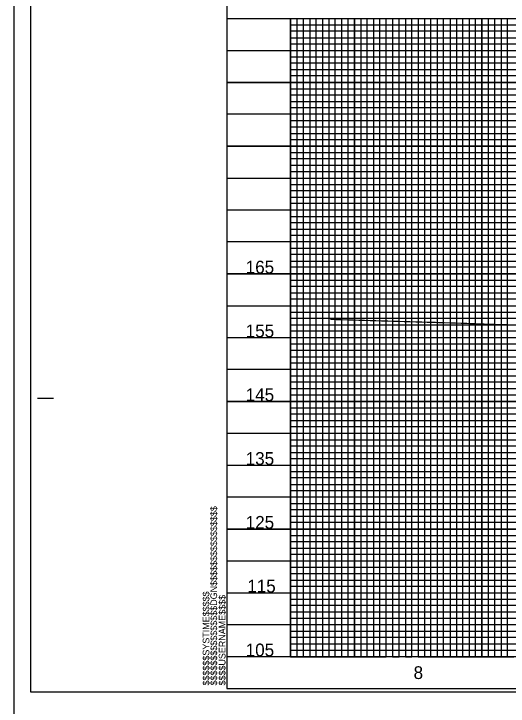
# Model space of a CAD drawing. Extents: x 573468 to 580768, y -57414 to -51768.
# Drawn here: x 578678 to 579066, y -56302 to -55760 of the extents above; entities that cross this region are included whole.
import ezdxf

# ---------------------------------------------------------------- set-up
doc = ezdxf.new("R2010")
doc.units = 0
for name, color, linetype in [('Exist Vertical Profile Ground Line', 7, 'Continuous'), ('Exist Vertical Profile Horizontal Axis Label Major', 7, 'Continuous'), ('Exist Vertical Profile Vertical Axis Label', 7, 'Continuous'), ('Sheet Cutting Line CELL', 7, 'Continuous'), ('Sheet DOT Grid CELL', 7, 'Continuous'), ('Sheet Layout Profile Border Port 2', 7, 'Continuous'), ('Sheet Plot Border Inside CELL', 7, 'Continuous'), ('Sheet Plot Border Outside CELL', 7, 'Continuous'), ('Sheet Profile CELL', 7, 'Continuous'), ('Sheet Profile Grid Major CELL', 7, 'Continuous'), ('Sheet Profile Grid Middle CELL', 7, 'Continuous'), ('Sheet Profile Grid Minor CELL', 7, 'Continuous')]:
    doc.layers.add(name, color=color, linetype=linetype)

msp = doc.modelspace()

# ---------------------------------------------------------------- linework, layer by layer
at = {"layer": 'Exist Vertical Profile Ground Line'}
msp.add_lwpolyline([(578926.4, -55999.16), (578928.22, -55999.2), (578930.86, -55999.28), (578932.24, -55999.32), (578935.32, -55999.41), (578939.77, -55999.54), (578944.23, -55999.68), (578948.69, -55999.81), (578953.15, -55999.94), (578957.6, -56000.07), (578957.91, -56000.08), (578958.28, -56000.09), (578962.06, -56000.2), (578966.52, -56000.34), (578968.16, -56000.38), (578970.97, -56000.45), (578971.32, -56000.46), (578975.43, -56000.59), (578979.89, -56000.72), (578984.34, -56000.85), (578988.8, -56000.99), (578993.26, -56001.12), (578996.61, -56001.22), (578997.97, -56001.25), (579002.17, -56001.38), (579006.87, -56001.52), (579008.82, -56001.58), (579011.09, -56001.65), (579015.54, -56001.79), (579020, -56001.93), (579024.46, -56002.07), (579028.91, -56002.22), (579033.37, -56002.36), (579035.51, -56002.43), (579037.35, -56002.49), (579037.83, -56002.51), (579039.87, -56002.57), (579042.28, -56002.65), (579046.95, -56002.8), (579050.67, -56002.92), (579051.2, -56002.93), (579053.6, -56003.01), (579055.65, -56003.08), (579060.11, -56003.22), (579064.57, -56003.36), (579069.02, -56003.5)], dxfattribs=at)
at = {"layer": 'Sheet Cutting Line CELL'}
msp.add_line((578678.21, -55213.55), (578678.21, -56313.55), dxfattribs=at)
at = {"layer": 'Sheet DOT Grid CELL'}
for p, q in [((578845.21, -55763.55), (580345.1, -55763.55)), ((578895.21, -55763.55), (578895.21, -56263.55)), ((578945.21, -55763.55), (578945.21, -56263.55)), ((578995.21, -55763.55), (578995.21, -56263.55)), ((579045.21, -55763.55), (579045.21, -56263.55)), ((578845.21, -55813.55), (580345.1, -55813.55)), ((578845.21, -55863.55), (580345.1, -55863.55)), ((578845.21, -55913.55), (580345.1, -55913.55)), ((578845.21, -55963.55), (580345.1, -55963.55)), ((578845.21, -56013.55), (580345.1, -56013.55)), ((578845.21, -56063.55), (580345.1, -56063.55)), ((578845.21, -56113.55), (580345.1, -56113.55)), ((578845.21, -56163.55), (580345.1, -56163.55)), ((578845.21, -56213.55), (580345.1, -56213.55))]:
    msp.add_line(p, q, dxfattribs=at)
at = {"layer": 'Sheet Layout Profile Border Port 2'}
msp.add_lwpolyline([(578895.21, -55763.55), (580295.21, -55763.55), (580295.21, -56263.55), (578895.21, -56263.55)], close=True, dxfattribs=at)
at = {"layer": 'Sheet Plot Border Inside CELL'}
msp.add_lwpolyline([(578691.21, -56291.1), (580357.71, -56291.1), (580357.71, -55236), (578691.21, -55236)], close=True, dxfattribs=at)
at = {"layer": 'Sheet Plot Border Outside CELL'}
msp.add_lwpolyline([(578678.21, -56313.55), (580362.21, -56313.55), (580362.21, -55213.55), (578678.21, -55213.55)], close=True, dxfattribs=at)
at = {"layer": 'Sheet Profile CELL'}
for p, q in [((578845.21, -55763.55), (580345.21, -55763.55)), ((578696.71, -56061.05), (578709.21, -56061.05)), ((580345.21, -56263.55), (578845.21, -56263.55)), ((578845.21, -56288.55), (580345.21, -56288.55)), ((578845.21, -56288.55), (578845.21, -56288.55)), ((578845.21, -56288.55), (578845.21, -56288.55)), ((578845.21, -56288.55), (578845.21, -56288.55)), ((578845.21, -56288.55), (578845.21, -56288.55)), ((578845.21, -56288.55), (578845.21, -56288.55)), ((578845.21, -56288.55), (578845.21, -56288.55)), ((578845.21, -56288.55), (578845.21, -56288.55))]:
    msp.add_line(p, q, dxfattribs=at)
msp.add_lwpolyline([(580345.21, -55238.55), (578845.21, -55238.55), (578845.21, -56288.55), (580345.21, -56288.55)], close=True, dxfattribs=at)
msp.add_lwpolyline([(578882.71, -56288.55), (578882.71, -56288.55)], dxfattribs=at)
at = {"layer": 'Sheet Profile Grid Major CELL'}
msp.add_line((578845.21, -56263.55), (578845.21, -56263.55), dxfattribs=at)
for points in [[(578895.21, -55763.55), (578895.21, -56263.55), (578945.21, -56263.55), (578945.21, -55763.55), (578995.21, -55763.55), (578995.21, -56263.55), (579045.21, -56263.55), (579045.21, -55763.55), (579095.21, -55763.55)], [(580345.21, -55813.55), (578845.21, -55813.55)], [(580345.21, -55863.55), (578845.21, -55863.55), (578845.21, -55913.55), (580345.21, -55913.55)], [(580345.21, -55963.55), (578845.21, -55963.55), (578845.21, -56013.55), (580345.21, -56013.55)], [(580345.21, -56063.55), (578845.21, -56063.55), (578845.21, -56113.55), (580345.21, -56113.55)], [(580345.21, -56163.55), (578845.21, -56163.55), (578845.21, -56163.55), (578845.21, -56213.55), (580345.21, -56213.55)], [(580345.21, -56263.55), (578845.21, -56263.55)]]:
    msp.add_lwpolyline(points, dxfattribs=at)
at = {"layer": 'Sheet Profile Grid Middle CELL'}
for points in [[(578870.21, -55763.55), (578920.21, -55763.55), (578920.21, -56263.55), (578970.21, -56263.55), (578970.21, -55763.55), (579020.21, -55763.55), (579020.21, -56263.55), (579070.21, -56263.55)], [(578845.21, -55788.55), (580345.21, -55788.55)], [(580345.21, -55838.55), (578845.21, -55838.55), (578845.21, -55888.55), (580345.21, -55888.55)], [(580345.21, -55938.55), (578845.21, -55938.55), (578845.21, -55988.55), (580345.21, -55988.55)], [(580345.21, -56038.55), (578845.21, -56038.55), (578845.21, -56088.55), (580345.21, -56088.55)], [(580345.21, -56138.55), (578845.21, -56138.55), (578845.21, -56188.55), (580345.21, -56188.55)], [(580345.21, -56238.55), (578845.21, -56238.55)]]:
    msp.add_lwpolyline(points, dxfattribs=at)
at = {"layer": 'Sheet Profile Grid Minor CELL'}
for p, q in [((578895.21, -55768.55), (580295.21, -55768.55)), ((580295.21, -55773.55), (578895.21, -55773.55)), ((578895.21, -55778.55), (580295.21, -55778.55)), ((580295.21, -55783.55), (578895.21, -55783.55)), ((578895.21, -55793.55), (580295.21, -55793.55)), ((580295.21, -55798.55), (578895.21, -55798.55)), ((578895.21, -55803.55), (580295.21, -55803.55)), ((580295.21, -55808.55), (578895.21, -55808.55)), ((578895.21, -55818.55), (580295.21, -55818.55)), ((580295.21, -55823.55), (578895.21, -55823.55)), ((578895.21, -55828.55), (580295.21, -55828.55)), ((580295.21, -55833.55), (578895.21, -55833.55)), ((578895.21, -55843.55), (580295.21, -55843.55)), ((580295.21, -55848.55), (578895.21, -55848.55)), ((578895.21, -55853.55), (580295.21, -55853.55)), ((580295.21, -55858.55), (578895.21, -55858.55)), ((578895.21, -55868.55), (580295.21, -55868.55)), ((580295.21, -55873.55), (578895.21, -55873.55)), ((578895.21, -55878.55), (580295.21, -55878.55)), ((580295.21, -55883.55), (578895.21, -55883.55)), ((578895.21, -55893.55), (580295.21, -55893.55)), ((580295.21, -55898.55), (578895.21, -55898.55)), ((578895.21, -55903.55), (580295.21, -55903.55)), ((580295.21, -55908.55), (578895.21, -55908.55)), ((578895.21, -55918.55), (580295.21, -55918.55)), ((580295.21, -55923.55), (578895.21, -55923.55)), ((578895.21, -55928.55), (580295.21, -55928.55)), ((580295.21, -55933.55), (578895.21, -55933.55)), ((578895.21, -55943.55), (580295.21, -55943.55)), ((580295.21, -55948.55), (578895.21, -55948.55)), ((578895.21, -55953.55), (580295.21, -55953.55)), ((580295.21, -55958.55), (578895.21, -55958.4)), ((578895.21, -55968.55), (580295.21, -55968.55)), ((580295.21, -55973.55), (578895.21, -55973.55)), ((578895.21, -55978.55), (580295.21, -55978.55)), ((580295.21, -55983.55), (578895.21, -55983.55)), ((578895.21, -55993.55), (580295.21, -55993.55)), ((580295.21, -55998.55), (578895.21, -55998.55)), ((578895.21, -56003.55), (580295.21, -56003.55)), ((580295.21, -56008.55), (578895.21, -56008.55)), ((578895.21, -56018.55), (580295.21, -56018.55)), ((580295.21, -56023.55), (578895.21, -56023.55)), ((578895.21, -56028.55), (580295.21, -56028.55)), ((580295.21, -56033.55), (578895.21, -56033.55)), ((578895.21, -56043.55), (580295.21, -56043.55)), ((580295.21, -56048.55), (578895.21, -56048.55)), ((578895.21, -56053.55), (580295.21, -56053.55)), ((580295.21, -56058.55), (578895.21, -56058.55)), ((578895.21, -56068.55), (580295.21, -56068.55)), ((580295.21, -56073.55), (578895.21, -56073.55)), ((578895.21, -56078.55), (580295.21, -56078.55)), ((580295.21, -56083.55), (578895.21, -56083.55)), ((578895.21, -56093.55), (580295.21, -56093.55)), ((580295.21, -56098.55), (578895.21, -56098.55)), ((578895.21, -56103.55), (580295.21, -56103.55)), ((580295.21, -56108.55), (578895.21, -56108.55)), ((578895.21, -56118.55), (580295.21, -56118.55)), ((580295.21, -56123.55), (578895.21, -56123.55)), ((578895.21, -56128.55), (580295.21, -56128.55)), ((580295.21, -56133.55), (578895.21, -56133.55)), ((578895.21, -56143.55), (580295.21, -56143.55)), ((580295.21, -56148.55), (578895.21, -56148.55)), ((578895.21, -56153.55), (580295.21, -56153.55)), ((580295.21, -56158.55), (578895.21, -56158.55)), ((578895.21, -56168.55), (580295.21, -56168.55)), ((580295.21, -56173.55), (578895.21, -56173.55)), ((578895.21, -56178.55), (580295.21, -56178.55)), ((580295.21, -56183.55), (578895.21, -56183.55)), ((578895.21, -56193.55), (580295.21, -56193.55)), ((580295.21, -56198.55), (578895.21, -56198.55)), ((578895.21, -56203.55), (580295.21, -56203.55)), ((580295.21, -56208.55), (578895.21, -56208.55)), ((578895.21, -56218.55), (580295.21, -56218.55)), ((580295.21, -56223.55), (578895.21, -56223.55)), ((578895.21, -56228.55), (580295.21, -56228.55)), ((580295.21, -56233.55), (578895.21, -56233.55)), ((578895.21, -56243.55), (580295.21, -56243.55)), ((580295.21, -56248.55), (578895.21, -56248.55)), ((578895.21, -56253.55), (580295.21, -56253.55)), ((578895.21, -56258.55), (580295.21, -56258.55))]:
    msp.add_line(p, q, dxfattribs=at)
for points in [[(578895.21, -55763.55), (578900.21, -55763.55), (578900.21, -56263.55), (578905.21, -56263.55), (578905.21, -55763.55), (578910.21, -55763.55), (578910.21, -56263.55), (578915.21, -56263.55), (578915.21, -55763.55), (578925.21, -55763.55), (578925.21, -56263.55), (578930.21, -56263.55), (578930.21, -55763.55), (578935.21, -55763.55), (578935.21, -56263.55), (578940.21, -56263.55), (578950.21, -56263.55), (578955.21, -56263.55), (578955.21, -55763.55), (578960.21, -55763.55), (578960.21, -56263.55), (578965.21, -56263.55), (578965.21, -55763.55), (578975.21, -55763.55), (578975.21, -56263.55), (578980.21, -56263.55), (578980.21, -55763.55), (578985.21, -55763.55), (578985.21, -56263.55), (578990.21, -56263.55), (578990.21, -55763.55), (579000.21, -55763.55), (579000.21, -56263.55), (579005.21, -56263.55), (579005.21, -55763.55), (579010.21, -55763.55), (579010.21, -56263.55), (579015.21, -56263.55), (579015.21, -55763.55), (579025.21, -55763.55), (579025.21, -56263.55), (579030.21, -56263.55), (579030.21, -55763.55), (579035.21, -55763.55), (579035.21, -56263.55), (579040.21, -56263.55), (579040.21, -55763.55), (579050.21, -55763.55), (579050.21, -56263.55), (579055.21, -56263.55), (579055.21, -55763.55), (579060.21, -55763.55), (579060.21, -56263.55), (579065.21, -56263.55), (579065.21, -55763.55), (579075.21, -55763.55)], [(578940.21, -56263.55), (578940.21, -55763.55), (578950.21, -55763.55), (578950.21, -56263.55)]]:
    msp.add_lwpolyline(points, dxfattribs=at)

# ---------------------------------------------------------------- texts
at = {"layer": 'Exist Vertical Profile Horizontal Axis Label Major'}
msp.add_text('8', height=10, dxfattribs=at).set_placement((578991.64, -56281.05))
at = {"layer": 'Exist Vertical Profile Vertical Axis Label'}
for s, p in [('165', (578860, -55963.3)), ('155', (578860, -56013.3)), ('145', (578860, -56063.3)), ('135', (578860, -56113.3)), ('125', (578860, -56163.3)), ('115', (578861.2, -56213.3)), ('105', (578860, -56263.3))]:
    msp.add_text(s, height=10, dxfattribs=at).set_placement(p)
at = {"layer": 'Sheet Profile CELL'}
for s, p in [('$$$$$$$$$$$$$$$$DGN$$$$$$$$$$$$$$$$', (578837.58, -56286.17)), ('$$$$$$SYSTIME$$$$$', (578831.53, -56286.17)), ('$$$$USERNAME$$$$', (578844.15, -56286.16))]:
    msp.add_text(s, height=5.25, rotation=90, dxfattribs=at).set_placement(p)

doc.saveas('drawing.dxf')
